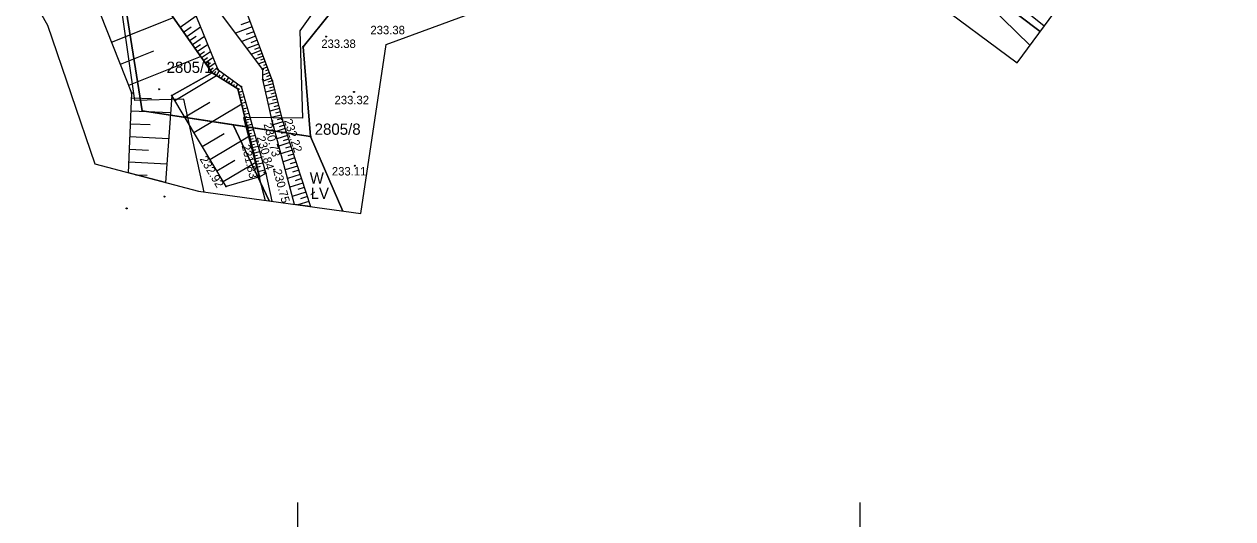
# Model space of a CAD drawing. Extents: x 6596400 to 6597200, y 5539751 to 5540251.
# Drawn here: x 6596725.7 to 6596833.2, y 5540002.1 to 5540046 of the extents above; entities that cross this region are included whole.
import ezdxf

# ---------------------------------------------------------------- set-up
doc = ezdxf.new("R2010")
doc.units = 0
for name, color, linetype in [('000 Inne (niezydentyfikowane)', 7, 'Continuous'), ('140-Punkty robocze', 7, 'Continuous'), ('203-punkt graniczny', 7, 'Continuous'), ('209-oznaczenie konturu klasyfikacyjnego', 7, 'Continuous'), ('210-oznaczenie konturu użytku gruntowego', 7, 'Continuous'), ('211-numer działki ewidencyjnej', 7, 'Continuous'), ('217-kontur klasyfikacyjny', 7, 'Continuous'), ('218-kontur użytku gruntowego', 7, 'Continuous'), ('219-działka ewidencyjna', 7, 'Continuous'), ('Linia obszaru zagospodarowania terenu', 7, 'Continuous'), ('pikieta sztuczna', 7, 'Continuous'), ('pikieta sztuczna-Atr2', 7, 'Continuous'), ('skarpa nieumocniona', 7, 'Continuous'), ('woda płynąca', 7, 'Continuous'), ('Wstawianie ramki sekcyjnej z opisem', 7, 'Continuous'), ('Zakres', 7, 'Continuous')]:
    doc.layers.add(name, color=color, linetype=linetype)

# ---------------------------------------------------------------- blocks, each defined once
blk = doc.blocks.new('203')
blk.add_circle((0, 0), 0.045)
blk = doc.blocks.new('RAMKA500K')
for p, q in [((0, 1), (0, 3.5)), ((350, 1), (350, 3.5)), ((400, 1), (400, 3.5))]:
    blk.add_line(p, q)
blk = doc.blocks.new('PIKIETA')
blk.add_circle((0, 0), 0.045)
blk = doc.blocks.new('PW01')
blk.add_circle((0, 0), 0.045)

msp = doc.modelspace()

# ---------------------------------------------------------------- linework, layer by layer
at = {"layer": '000 Inne (niezydentyfikowane)'}
for p, q in [((6596733.43, 5540044.45), (6596738.93, 5540046.64)), ((6596745.74, 5540046.27), (6596744.93, 5540045.97)), ((6596745.92, 5540045.8), (6596744.45, 5540045.24)), ((6596746.08, 5540045.36), (6596745.41, 5540045.11)), ((6596746.23, 5540044.96), (6596745.01, 5540044.5)), ((6596746.49, 5540044.27), (6596745.47, 5540043.88)), ((6596746.37, 5540044.6), (6596745.81, 5540044.39)), ((6596734.21, 5540042.49), (6596737.19, 5540043.68)), ((6596734.96, 5540040.62), (6596741.35, 5540043.17)), ((6596746.71, 5540043.69), (6596745.86, 5540043.37)), ((6596746.61, 5540043.97), (6596746.14, 5540043.79)), ((6596746.9, 5540043.2), (6596746.19, 5540042.93)), ((6596746.81, 5540043.44), (6596746.42, 5540043.29)), ((6596746.99, 5540042.95), (6596746.67, 5540042.83)), ((6596747.08, 5540042.71), (6596746.52, 5540042.5)), ((6596747.27, 5540042.22), (6596746.85, 5540042.06)), ((6596747.18, 5540042.46), (6596746.93, 5540042.37)), ((6596747.36, 5540041.98), (6596747.12, 5540041.88)), ((6596747.46, 5540041.73), (6596746.88, 5540041.51)), ((6596747.64, 5540041.24), (6596746.91, 5540040.97)), ((6596747.55, 5540041.49), (6596747.21, 5540041.36)), ((6596747.73, 5540040.99), (6596747.34, 5540040.89)), ((6596747.8, 5540040.73), (6596747.01, 5540040.52)), ((6596747.93, 5540040.19), (6596747.13, 5540039.99)), ((6596747.87, 5540040.46), (6596747.47, 5540040.36)), ((6596748, 5540039.92), (6596747.6, 5540039.82)), ((6596735.22, 5540039.5), (6596736.99, 5540039.42)), ((6596748.07, 5540039.65), (6596747.26, 5540039.44)), ((6596748.22, 5540039.09), (6596747.38, 5540038.88)), ((6596748.15, 5540039.37), (6596747.73, 5540039.27)), ((6596748.29, 5540038.81), (6596747.87, 5540038.7)), ((6596735.17, 5540038.34), (6596738.67, 5540038.18)), ((6596748.36, 5540038.53), (6596747.51, 5540038.31)), ((6596748.51, 5540037.95), (6596747.64, 5540037.73)), ((6596748.44, 5540038.24), (6596748.01, 5540038.13)), ((6596748.59, 5540037.66), (6596748.15, 5540037.54)), ((6596735.12, 5540037.18), (6596736.85, 5540037.1)), ((6596748.67, 5540037.36), (6596747.8, 5540037.08)), ((6596748.87, 5540036.76), (6596747.97, 5540036.47)), ((6596748.77, 5540037.07), (6596748.33, 5540036.92)), ((6596748.97, 5540036.46), (6596748.51, 5540036.31)), ((6596735.06, 5540036.04), (6596738.5, 5540035.88)), ((6596749.07, 5540036.14), (6596748.14, 5540035.84)), ((6596749.28, 5540035.5), (6596748.31, 5540035.18)), ((6596749.17, 5540035.82), (6596748.7, 5540035.67)), ((6596735.01, 5540034.91), (6596736.72, 5540034.83)), ((6596749.5, 5540034.83), (6596748.49, 5540034.5)), ((6596749.39, 5540035.17), (6596748.89, 5540035.01)), ((6596749.61, 5540034.49), (6596749.1, 5540034.32)), ((6596734.96, 5540033.79), (6596738.34, 5540033.63)), ((6596749.72, 5540034.14), (6596748.68, 5540033.8)), ((6596749.95, 5540033.42), (6596748.88, 5540033.07)), ((6596749.84, 5540033.78), (6596749.31, 5540033.61)), ((6596735.58, 5540032.65), (6596736.59, 5540032.61)), ((6596750.2, 5540032.68), (6596749.08, 5540032.31)), ((6596750.07, 5540033.05), (6596749.53, 5540032.87)), ((6596750.32, 5540032.3), (6596749.75, 5540032.11)), ((6596750.45, 5540031.91), (6596749.29, 5540031.53)), ((6596750.71, 5540031.11), (6596749.5, 5540030.72)), ((6596750.57, 5540031.51), (6596749.98, 5540031.32)), ((6596750.97, 5540030.28), (6596750, 5540029.97)), ((6596750.84, 5540030.7), (6596750.23, 5540030.5)), ((6596751.11, 5540029.86), (6596751.02, 5540029.83))]:
    msp.add_line(p, q, dxfattribs=at)
for points in [[(6596739.53, 5540045.77), (6596740.95, 5540046.77)], [(6596739.83, 5540045.34), (6596740.5, 5540045.8)], [(6596740.11, 5540044.94), (6596741.34, 5540045.8)], [(6596740.37, 5540044.57), (6596740.95, 5540044.97)], [(6596740.62, 5540044.22), (6596741.68, 5540044.97)], [(6596740.84, 5540043.9), (6596741.34, 5540044.24)], [(6596741.05, 5540043.6), (6596741.97, 5540044.24)], [(6596741.25, 5540043.32), (6596741.68, 5540043.62)], [(6596741.43, 5540043.06), (6596742.23, 5540043.62)], [(6596741.6, 5540042.82), (6596741.97, 5540043.08)], [(6596741.75, 5540042.59), (6596742.44, 5540043.07)], [(6596741.9, 5540042.38), (6596742.22, 5540042.6)], [(6596742.05, 5540042.17), (6596742.64, 5540042.59)], [(6596742.19, 5540041.96), (6596742.47, 5540042.15)], [(6596742.34, 5540041.75), (6596742.81, 5540042.17)], [(6596742.54, 5540041.6), (6596742.69, 5540041.85)], [(6596742.76, 5540041.47), (6596743.03, 5540041.9)], [(6596739.05, 5540039.24), (6596742.77, 5540041.46)], [(6596742.97, 5540041.34), (6596743.1, 5540041.54)], [(6596743.19, 5540041.2), (6596743.44, 5540041.6)], [(6596743.4, 5540041.07), (6596743.52, 5540041.26)], [(6596743.62, 5540040.93), (6596743.85, 5540041.3)], [(6596743.84, 5540040.8), (6596743.94, 5540040.97)], [(6596744.05, 5540040.66), (6596744.26, 5540041)], [(6596744.27, 5540040.53), (6596744.37, 5540040.69)], [(6596744.48, 5540040.4), (6596744.67, 5540040.7)], [(6596744.68, 5540040.25), (6596744.84, 5540040.29)], [(6596744.74, 5540040), (6596745.07, 5540040.08)], [(6596744.8, 5540039.75), (6596744.97, 5540039.79)], [(6596739.92, 5540037.78), (6596742.16, 5540039.11)], [(6596740.75, 5540036.4), (6596745, 5540038.94)], [(6596744.86, 5540039.51), (6596745.21, 5540039.59)], [(6596744.92, 5540039.26), (6596745.1, 5540039.3)], [(6596744.98, 5540039.01), (6596745.35, 5540039.1)], [(6596745.04, 5540038.76), (6596745.23, 5540038.81)], [(6596745.1, 5540038.52), (6596745.49, 5540038.61)], [(6596745.16, 5540038.27), (6596745.36, 5540038.32)], [(6596745.22, 5540038.02), (6596745.63, 5540038.12)], [(6596745.28, 5540037.78), (6596745.49, 5540037.83)], [(6596745.34, 5540037.53), (6596745.77, 5540037.63)], [(6596745.4, 5540037.28), (6596745.62, 5540037.34)], [(6596745.46, 5540037.04), (6596745.91, 5540037.14)], [(6596745.52, 5540036.79), (6596745.75, 5540036.84)], [(6596745.58, 5540036.54), (6596746.05, 5540036.66)], [(6596741.49, 5540035.15), (6596743.43, 5540036.3)], [(6596742.17, 5540034.01), (6596745.69, 5540036.11)], [(6596745.64, 5540036.29), (6596745.88, 5540036.35)], [(6596745.7, 5540036.05), (6596746.19, 5540036.17)], [(6596745.76, 5540035.8), (6596746.01, 5540035.86)], [(6596745.82, 5540035.55), (6596746.33, 5540035.68)], [(6596745.88, 5540035.31), (6596746.14, 5540035.37)], [(6596745.94, 5540035.06), (6596746.47, 5540035.19)], [(6596746, 5540034.81), (6596746.27, 5540034.88)], [(6596746.06, 5540034.57), (6596746.61, 5540034.7)], [(6596746.12, 5540034.32), (6596746.4, 5540034.39)], [(6596742.79, 5540032.98), (6596744.39, 5540033.93)], [(6596743.35, 5540032.04), (6596746.26, 5540033.77)], [(6596746.18, 5540034.07), (6596746.75, 5540034.21)], [(6596746.24, 5540033.82), (6596746.53, 5540033.89)], [(6596746.3, 5540033.58), (6596746.89, 5540033.72)], [(6596746.37, 5540033.33), (6596746.66, 5540033.4)], [(6596746.46, 5540032.94), (6596747.07, 5540033.08)]]:
    msp.add_lwpolyline(points, dxfattribs=at)
at = {"layer": '217-kontur klasyfikacyjny'}
for points in [[(6596815.12, 5540044.15), (6596806.51, 5540052.58)], [(6596806.51, 5540052.58), (6596815.12, 5540044.15)], [(6596816.03, 5540045.39), (6596806.51, 5540052.58)], [(6596736.14, 5540038.34), (6596734.44, 5540049.18)], [(6596753.05, 5540047.22), (6596750.47, 5540044.03)], [(6596750.47, 5540044.03), (6596751.11, 5540036.04)], [(6596744.25, 5540037.09), (6596736.14, 5540038.34)], [(6596751.11, 5540036.04), (6596744.25, 5540037.09)], [(6596744.25, 5540037.09), (6596747.44, 5540030.32)], [(6596747.44, 5540030.32), (6596744.25, 5540037.09)], [(6596751.11, 5540036.04), (6596753.99, 5540029.42)], [(6596753.99, 5540029.42), (6596751.11, 5540036.04)]]:
    msp.add_lwpolyline(points, dxfattribs=at)
at = {"layer": '218-kontur użytku gruntowego'}
for points in [[(6596815.12, 5540044.15), (6596806.51, 5540052.58)], [(6596806.51, 5540052.58), (6596815.12, 5540044.15)], [(6596816.03, 5540045.39), (6596806.51, 5540052.58)], [(6596806.51, 5540052.58), (6596816.03, 5540045.39)], [(6596736.14, 5540038.34), (6596734.44, 5540049.18)], [(6596734.44, 5540049.18), (6596736.14, 5540038.34)], [(6596753.05, 5540047.22), (6596750.47, 5540044.03)], [(6596750.47, 5540044.03), (6596753.05, 5540047.22)], [(6596750.47, 5540044.03), (6596751.11, 5540036.04)], [(6596751.11, 5540036.04), (6596750.47, 5540044.03)], [(6596744.25, 5540037.09), (6596736.14, 5540038.34)], [(6596736.14, 5540038.34), (6596744.25, 5540037.09)], [(6596751.11, 5540036.04), (6596744.25, 5540037.09)], [(6596744.25, 5540037.09), (6596747.44, 5540030.32)], [(6596747.44, 5540030.32), (6596744.25, 5540037.09)], [(6596744.25, 5540037.09), (6596751.11, 5540036.04)], [(6596751.11, 5540036.04), (6596753.99, 5540029.42)], [(6596753.99, 5540029.42), (6596751.11, 5540036.04)]]:
    msp.add_lwpolyline(points, dxfattribs=at)
at = {"layer": '219-działka ewidencyjna'}
for points in [[(6596816.03, 5540045.39), (6596806.51, 5540052.58)], [(6596736.14, 5540038.34), (6596734.44, 5540049.18)], [(6596750.47, 5540044.03), (6596753.05, 5540047.22)], [(6596751.11, 5540036.04), (6596750.47, 5540044.03)], [(6596751.11, 5540036.04), (6596736.14, 5540038.34)]]:
    msp.add_lwpolyline(points, dxfattribs=at)
at = {"layer": 'Linia obszaru zagospodarowania terenu'}
for points in [[(6596816.37, 5540045.85), (6596805.78, 5540054.39), (6596786.09, 5540061.13), (6596752.3, 5540048.46), (6596750.16, 5540045.43), (6596750.4, 5540037.69), (6596745.15, 5540037.73), (6596747.1, 5540030.37)], [(6596741.65, 5540031.11), (6596739.85, 5540039.37), (6596735.5, 5540039.24), (6596733.94, 5540050.18), (6596728.96, 5540057.84)]]:
    msp.add_lwpolyline(points, dxfattribs=at)
at = {"layer": 'skarpa nieumocniona'}
for points in [[(6596733.94, 5540086.32), (6596732.43, 5540082.43), (6596735.19, 5540080.23), (6596736.14, 5540074.83), (6596737.01, 5540060.57), (6596734.88, 5540056.12), (6596737.49, 5540048.7), (6596742.37, 5540041.71), (6596738.78, 5540039.69), (6596738.22, 5540031.96), (6596734.92, 5540032.83), (6596735.24, 5540039.91), (6596732.47, 5540046.87), (6596731.97, 5540049.93), (6596729.74, 5540057.45), (6596728.56, 5540067.81), (6596728.25, 5540071.52), (6596725.74, 5540083.5), (6596726.85, 5540087.53)], [(6596733.94, 5540086.32), (6596732.43, 5540082.43), (6596735.19, 5540080.23), (6596736.14, 5540074.83), (6596737.01, 5540060.57), (6596734.88, 5540056.12), (6596737.49, 5540048.7), (6596742.37, 5540041.71), (6596738.78, 5540039.69), (6596738.22, 5540031.96), (6596734.92, 5540032.83), (6596735.24, 5540039.91), (6596732.47, 5540046.87), (6596731.97, 5540049.93), (6596729.74, 5540057.45), (6596728.56, 5540067.81), (6596728.25, 5540071.52), (6596725.74, 5540083.5), (6596726.85, 5540087.53)], [(6596747.16, 5540032.77), (6596746.58, 5540032.45), (6596744.67, 5540040.28), (6596742.37, 5540041.71), (6596737.49, 5540048.7), (6596734.88, 5540056.12), (6596737.01, 5540060.57), (6596737.04, 5540056.69), (6596739.69, 5540049.9), (6596742.87, 5540042.02), (6596744.95, 5540040.49)], [(6596747.16, 5540032.77), (6596746.58, 5540032.45), (6596744.67, 5540040.28), (6596742.37, 5540041.71), (6596737.49, 5540048.7), (6596734.88, 5540056.12), (6596737.01, 5540060.57), (6596737.04, 5540056.69), (6596739.69, 5540049.9), (6596742.87, 5540042.02), (6596744.95, 5540040.49)], [(6596764.63, 5540056.07), (6596757.72, 5540051.48), (6596748.68, 5540048.72), (6596744.91, 5540048.46), (6596747.72, 5540041.03), (6596748.61, 5540037.56), (6596751.13, 5540029.81), (6596749.69, 5540030.01), (6596747.71, 5540037.43), (6596746.88, 5540041.11), (6596746.88, 5540042.02), (6596743.2, 5540046.89), (6596742.01, 5540050.53), (6596747.46, 5540050.98), (6596751.88, 5540051.19), (6596756.01, 5540053.96), (6596757.53, 5540054.97), (6596761.73, 5540059.12)], [(6596764.63, 5540056.07), (6596757.72, 5540051.48), (6596748.68, 5540048.72), (6596744.91, 5540048.46), (6596747.72, 5540041.03), (6596748.61, 5540037.56), (6596751.13, 5540029.81), (6596749.69, 5540030.01), (6596747.71, 5540037.43), (6596746.88, 5540041.11), (6596746.88, 5540042.02), (6596743.2, 5540046.89), (6596742.01, 5540050.53), (6596747.46, 5540050.98), (6596751.88, 5540051.19), (6596756.01, 5540053.96), (6596757.53, 5540054.97), (6596761.73, 5540059.12)], [(6596743.61, 5540031.61), (6596738.78, 5540039.69), (6596742.37, 5540041.71), (6596744.67, 5540040.28), (6596746.58, 5540032.45)], [(6596743.61, 5540031.61), (6596738.78, 5540039.69), (6596742.37, 5540041.71), (6596744.67, 5540040.28), (6596746.58, 5540032.45)]]:
    msp.add_lwpolyline(points, close=True, dxfattribs=at)
at = {"layer": 'woda płynąca'}
for points in [[(6596736.53, 5540085.88), (6596736.56, 5540080.1), (6596736.48, 5540078.77), (6596736.14, 5540074.83), (6596737.01, 5540060.57), (6596737.04, 5540056.69), (6596739.69, 5540049.9), (6596742.87, 5540042.02), (6596744.95, 5540040.49), (6596747.16, 5540032.77), (6596747.69, 5540030.29)], [(6596749.69, 5540030.01), (6596747.71, 5540037.43), (6596746.88, 5540041.11), (6596746.88, 5540042.02), (6596743.2, 5540046.89)]]:
    msp.add_lwpolyline(points, dxfattribs=at)
at = {"layer": 'Zakres'}
msp.add_lwpolyline([(6596822.22, 5540097.5), (6596800.39, 5540105.4), (6596755.76, 5540121.45), (6596697.73, 5540120.74), (6596659.35, 5540133.92), (6596647.64, 5540109.28), (6596697.73, 5540077), (6596721.01, 5540057.77), (6596727.72, 5540045.95), (6596731.95, 5540033.61), (6596741.17, 5540031.18), (6596755.59, 5540029.2), (6596757.85, 5540044.22), (6596787.25, 5540055.04), (6596806.3, 5540048.33), (6596813.97, 5540042.6), (6596833.15, 5540068.58), (6596822.3, 5540077.75)], close=True, dxfattribs=at)

# ---------------------------------------------------------------- block references
at = {"layer": '140-Punkty robocze'}
for p in [(6596752.51, 5540044.93), (6596742.87, 5540042.02), (6596746.88, 5540042.02), (6596742.37, 5540041.71), (6596746.88, 5540041.11), (6596747.72, 5540041.03), (6596735.24, 5540039.91), (6596737.66, 5540040.25), (6596738.78, 5540039.69), (6596744.67, 5540040.28), (6596744.95, 5540040.49), (6596754.99, 5540040.01), (6596748.61, 5540037.56), (6596747.71, 5540037.43), (6596755.06, 5540033.45), (6596746.58, 5540032.45), (6596747.03, 5540032.85), (6596747.16, 5540032.77), (6596747.9, 5540033.1), (6596743.61, 5540031.61), (6596738.13, 5540030.71), (6596734.77, 5540029.65)]:
    msp.add_blockref('PIKIETA', p, dxfattribs=at)
at = {"layer": '203-punkt graniczny'}
for p in [(6596750.47, 5540044.03), (6596736.14, 5540038.34), (6596751.11, 5540036.04)]:
    msp.add_blockref('203', p, dxfattribs=at)
at = {"layer": 'pikieta sztuczna'}
for p in [(6596752.51, 5540044.93), (6596754.99, 5540040.01), (6596748.61, 5540037.56), (6596747.71, 5540037.43), (6596755.06, 5540033.45), (6596746.58, 5540032.45), (6596747.16, 5540032.77), (6596747.9, 5540033.1), (6596743.61, 5540031.61)]:
    msp.add_blockref('PW01', p, dxfattribs=at)
at = {"layer": 'Wstawianie ramki sekcyjnej z opisem'}
for p in [(6596400, 5540000), (6596800, 5540000)]:
    msp.add_blockref('RAMKA500K', p, dxfattribs=at)

# ---------------------------------------------------------------- texts
at = {"layer": '209-oznaczenie konturu klasyfikacyjnego'}
msp.add_text('ŁV', height=1, dxfattribs=at).set_placement((6596751.13, 5540030.5))
at = {"layer": '210-oznaczenie konturu użytku gruntowego'}
msp.add_text('W', height=1, dxfattribs=at).set_placement((6596751.05, 5540031.86))
at = {"layer": '211-numer działki ewidencyjnej'}
for s, p in [('2805/1', (6596738.32, 5540041.7)), ('2805/8', (6596751.49, 5540036.2))]:
    msp.add_text(s, height=1, dxfattribs=at).set_placement(p)
at = {"layer": 'pikieta sztuczna-Atr2'}
for s, p in [('233.38', (6596756.45, 5540045.14)), ('233.38', (6596752.08, 5540043.92)), ('233.32', (6596753.26, 5540038.92)), ('233.11', (6596753.02, 5540032.58))]:
    msp.add_text(s, height=0.75, dxfattribs=at).set_placement(p)
for s, rotation, p in [('232.22', 287.996, (6596748.75, 5540037.47)), ('230.73', 284.972, (6596746.94, 5540037.14)), ('230.84', 285.975, (6596746.33, 5540035.97)), ('232.92', 300.87, (6596741.24, 5540034.04)), ('231.83', 283.709, (6596744.99, 5540035.24)), ('230.75', 284.972, (6596747.79, 5540033.03))]:
    msp.add_text(s, height=0.75, rotation=rotation, dxfattribs=at).set_placement(p)

doc.saveas('drawing.dxf')
